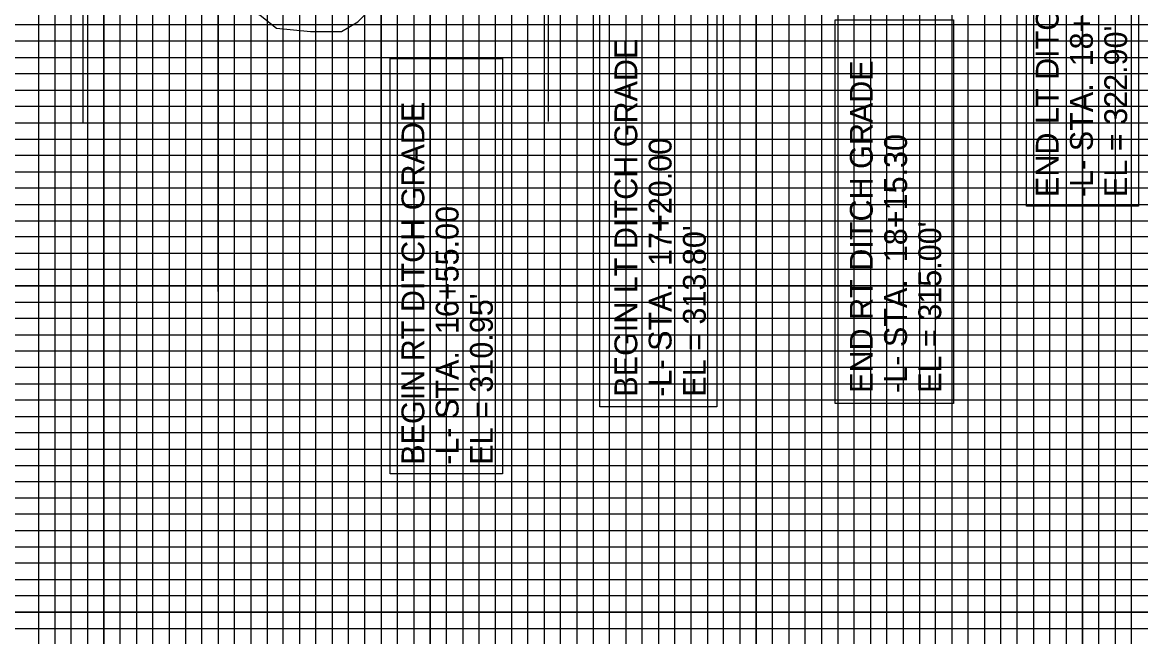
# Model space of a CAD drawing. Extents: x 574125 to 576234, y -56630 to -55530.
# Drawn here: x 575081.8 to 575424.7, y -56337.3 to -56149.1 of the extents above; entities that cross this region are included whole.
import ezdxf

# ---------------------------------------------------------------- set-up
doc = ezdxf.new("R2010")
doc.units = 0
for name, color, linetype in [('Exist Profile Cell', 7, 'Continuous'), ('Exist Vertical Profile Ground Line', 7, 'Continuous'), ('Prop Grid Mask', 7, 'Continuous'), ('Prop Roadway Bridge', 7, 'Continuous'), ('Prop VPI Ditch Grade Left Label', 7, 'Continuous'), ('Prop VPI Ditch Grade Right Label', 7, 'Continuous'), ('Sheet DOT Grid CELL', 7, 'Continuous'), ('Sheet Profile Grid Major CELL', 7, 'Continuous'), ('Sheet Profile Grid Middle CELL', 7, 'Continuous'), ('Sheet Profile Grid Minor CELL', 7, 'Continuous')]:
    doc.layers.add(name, color=color, linetype=linetype)

msp = doc.modelspace()

# ---------------------------------------------------------------- linework, layer by layer
at = {"layer": 'Exist Profile Cell'}
msp.add_line((574556.81, -56179.85), (576005.64, -56179.85), dxfattribs=at)
at = {"layer": 'Exist Vertical Profile Ground Line'}
msp.add_lwpolyline([(575135.67, -56116.85), (575139.67, -56134.8), (575142.47, -56131.35), (575143.87, -56143.35), (575148.27, -56144.55), (575154.67, -56146.85), (575159.67, -56150.85), (575170.17, -56151.85), (575179.67, -56151.85), (575184.67, -56148.85), (575190.67, -56142.85), (575197.67, -56124.35), (575204.67, -56114.85)], dxfattribs=at)
at = {"layer": 'Prop Grid Mask'}
msp.add_line((575211.81, -56160.12), (575211.81, -56125.1), dxfattribs=at)
for points in [[(575424, -56205.39), (575389.62, -56205.39), (575389.62, -56089.34), (575424, -56089.34)], [(575294.76, -56266.92), (575258.86, -56266.92), (575258.86, -56141.05), (575294.76, -56141.05)], [(575367.27, -56265.86), (575330.95, -56265.86), (575330.95, -56148.28), (575367.27, -56148.28)], [(575229.04, -56287.42), (575194.57, -56287.42), (575194.57, -56160.12), (575229.04, -56160.12)]]:
    msp.add_lwpolyline(points, close=True, dxfattribs=at)
at = {"layer": 'Prop Roadway Bridge'}
for p, q in [((575243.16, -56179.46), (575243.16, -56041.44)), ((575100.46, -56179.87), (575100.46, -56062.85)), ((575191.85, -56230.81), (575191.85, -56065.17)), ((575141.85, -56231.51), (575141.85, -56072.67))]:
    msp.add_line(p, q, dxfattribs=at)
at = {"layer": 'Sheet DOT Grid CELL'}
for p, q in [((575106.81, -55554.85), (575106.81, -56579.85)), ((575156.81, -55554.85), (575156.81, -56579.85)), ((575206.81, -55554.85), (575206.81, -56579.85)), ((575256.81, -55554.85), (575256.81, -56579.85)), ((575306.81, -55554.85), (575306.81, -56579.85)), ((575356.81, -55554.85), (575356.81, -56579.85)), ((575406.81, -55554.85), (575406.81, -56579.85)), ((574506.81, -56179.85), (576006.81, -56179.85)), ((574506.81, -56229.85), (576006.81, -56229.85)), ((574506.81, -56279.85), (576006.81, -56279.85)), ((574506.81, -56329.85), (576006.81, -56329.85))]:
    msp.add_line(p, q, dxfattribs=at)
at = {"layer": 'Sheet Profile Grid Major CELL'}
for points in [[(575056.81, -56579.85), (575106.81, -56579.85), (575106.81, -55554.85)], [(575156.81, -55554.85), (575156.81, -56579.85), (575206.81, -56579.85), (575206.81, -55554.85)], [(575256.81, -55554.85), (575256.81, -56579.85), (575306.81, -56579.85), (575306.81, -55554.85)], [(575356.81, -55554.85), (575356.81, -56579.85), (575406.81, -56579.85), (575406.81, -55554.85)], [(576006.81, -56229.85), (574506.81, -56229.85), (574506.81, -56179.85), (576006.81, -56179.85)], [(576006.81, -56329.85), (574506.81, -56329.85), (574506.81, -56279.85), (576006.81, -56279.85)]]:
    msp.add_lwpolyline(points, dxfattribs=at)
at = {"layer": 'Sheet Profile Grid Middle CELL'}
for points in [[(575131.81, -55554.85), (575131.81, -56579.85), (575181.81, -56579.85), (575181.81, -55554.85)], [(575231.81, -55554.85), (575231.81, -56579.85), (575281.81, -56579.85), (575281.81, -55554.85)], [(575331.81, -55554.85), (575331.81, -56579.85), (575381.81, -56579.85), (575381.81, -55554.85)], [(576006.81, -56154.85), (574506.81, -56154.85), (574506.81, -56204.85), (576006.81, -56204.85)], [(576006.81, -56254.85), (574506.81, -56254.85), (574506.81, -56304.85), (576006.81, -56304.85)]]:
    msp.add_lwpolyline(points, dxfattribs=at)
at = {"layer": 'Sheet Profile Grid Minor CELL'}
for points in [[(575086.81, -56579.85), (575086.81, -55554.85)], [(575091.81, -55554.85), (575091.81, -56579.85), (575096.81, -56579.85), (575096.81, -55554.85)], [(575101.81, -55554.85), (575101.81, -56579.85), (575111.81, -56579.85), (575111.81, -55554.85)], [(575116.81, -55554.85), (575116.81, -56579.85), (575116.81, -56579.85), (575121.81, -56579.85), (575121.81, -55554.85)], [(575126.81, -55554.85), (575126.81, -56579.85), (575136.81, -56579.85), (575136.81, -55554.85)], [(575141.81, -55554.85), (575141.81, -56579.85), (575146.81, -56579.85), (575146.81, -55554.85)], [(575151.81, -55554.85), (575151.81, -56579.85), (575161.81, -56579.85), (575161.81, -55554.85)], [(575166.81, -55554.85), (575166.81, -56579.85), (575171.81, -56579.85), (575171.81, -55554.85)], [(575176.81, -55554.85), (575176.81, -56579.85), (575186.81, -56579.85), (575186.81, -55554.85)], [(575191.81, -55554.85), (575191.81, -56579.85), (575196.81, -56579.85), (575196.81, -55554.85)], [(575201.81, -55554.85), (575201.81, -56579.85), (575211.81, -56579.85), (575211.81, -55554.85)], [(575216.81, -55554.85), (575216.81, -56579.85), (575221.81, -56579.85), (575221.81, -55554.85)], [(575226.81, -55554.85), (575226.81, -56579.85), (575236.81, -56579.85), (575236.81, -55554.85)], [(575241.81, -55554.85), (575241.81, -56579.85), (575246.81, -56579.85), (575246.81, -55554.85)], [(575251.81, -55554.85), (575251.81, -56579.85), (575261.81, -56579.85), (575261.81, -55554.85)], [(575266.81, -55554.85), (575266.81, -56579.85)], [(575266.81, -56579.85), (575271.81, -56579.85), (575271.81, -55555.45)], [(575276.81, -55555.45), (575276.81, -56579.85), (575286.81, -56579.85), (575286.81, -55554.85)], [(575291.81, -55554.85), (575291.81, -56579.85), (575296.81, -56579.85), (575296.81, -55554.85)], [(575301.81, -55554.85), (575301.81, -56579.85), (575311.81, -56579.85), (575311.81, -55554.85)], [(575316.81, -55554.85), (575316.81, -56579.85), (575321.81, -56579.85), (575321.81, -55554.85)], [(575326.81, -55554.85), (575326.81, -56579.85), (575336.81, -56579.85), (575336.81, -55554.85)], [(575341.81, -55554.85), (575341.81, -56579.85), (575346.81, -56579.85), (575346.81, -55554.85)], [(575351.81, -55554.85), (575351.81, -56579.85), (575361.81, -56579.85), (575361.81, -55554.85)], [(575366.81, -55554.85), (575366.81, -56579.85), (575371.81, -56579.85), (575371.81, -55554.85)], [(575376.81, -55554.85), (575376.81, -56579.85), (575386.81, -56579.85), (575386.81, -55554.85)], [(575391.81, -55554.85), (575391.81, -56579.85), (575396.81, -56579.85), (575396.81, -55554.85)], [(575401.81, -55554.85), (575401.81, -56579.85), (575411.81, -56579.85), (575411.81, -55554.85)], [(575416.81, -55554.85), (575416.81, -56579.85), (575421.81, -56579.85), (575421.81, -55554.85)], [(575956.81, -56149.85), (574556.81, -56149.85), (574556.81, -56159.85), (575956.81, -56159.85)], [(575956.81, -56164.85), (574556.81, -56164.85), (574556.81, -56169.85), (575956.81, -56169.85)], [(575956.81, -56174.85), (574556.81, -56174.85), (574556.81, -56184.85), (575956.81, -56184.85)], [(575956.81, -56189.85), (574556.81, -56189.85), (574556.81, -56194.85), (575956.81, -56194.85)], [(575956.81, -56199.85), (574556.81, -56199.85), (574556.81, -56209.85), (575956.81, -56209.85)], [(575956.81, -56214.85), (574556.81, -56214.85), (574556.81, -56219.85), (575956.81, -56219.85)], [(575956.81, -56224.85), (574556.81, -56224.85), (574556.81, -56234.85), (575956.81, -56234.85)], [(575956.81, -56239.85), (574556.81, -56239.85), (574556.81, -56244.85), (575956.81, -56244.85)], [(575956.81, -56249.85), (574556.81, -56249.85), (574556.81, -56259.85), (575956.81, -56259.85)], [(575956.81, -56264.85), (574556.81, -56264.85), (574556.81, -56269.85), (575956.81, -56269.85)], [(575956.81, -56274.85), (574556.81, -56274.85), (574556.81, -56284.85), (575956.81, -56284.85)], [(575956.81, -56289.85), (574556.81, -56289.85), (574556.81, -56294.85), (575956.81, -56294.85)], [(575956.81, -56299.85), (574556.81, -56299.85), (574556.81, -56309.85), (575956.81, -56309.85)], [(575956.81, -56314.85), (574556.81, -56314.85), (574556.81, -56319.85), (575956.81, -56319.85)], [(575956.81, -56324.85), (574556.81, -56324.85), (574556.81, -56334.85), (575956.81, -56334.85)]]:
    msp.add_lwpolyline(points, dxfattribs=at)

# ---------------------------------------------------------------- texts
at = {"layer": 'Prop VPI Ditch Grade Left Label'}
for s, p in [('END LT DITCH GRADE', (575399.51, -56202.6)), ('-L- STA.  18+50.00', (575410.01, -56202.6)), ("EL = 322.90'", (575420.51, -56202.6)), ('BEGIN LT DITCH GRADE', (575270.34, -56263.8)), ('-L- STA.  17+20.00', (575280.84, -56263.8)), ("EL = 313.80'", (575291.34, -56263.8))]:
    msp.add_text(s, height=7, rotation=90, dxfattribs=at).set_placement(p)
at = {"layer": 'Prop VPI Ditch Grade Right Label'}
for s, p in [('END RT DITCH GRADE', (575342.52, -56262.63)), ('BEGIN RT DITCH GRADE', (575205.04, -56284.68)), ('-L- STA.  18+15.30', (575353.02, -56262.63)), ('-L- STA.  16+55.00', (575215.54, -56284.68)), ("EL = 315.00'", (575363.52, -56262.63)), ("EL = 310.95'", (575226.04, -56284.68))]:
    msp.add_text(s, height=7, rotation=90, dxfattribs=at).set_placement(p)

doc.saveas('drawing.dxf')
